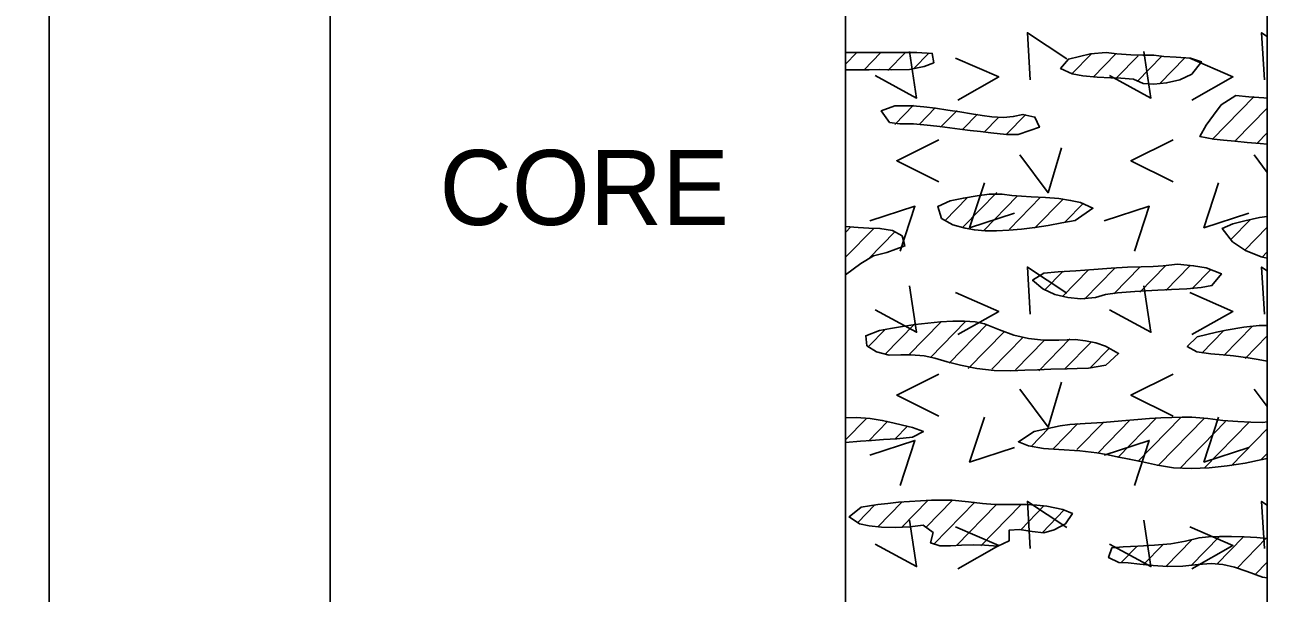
# Model space of a CAD drawing. Extents: x 0 to 0.833, y -0.32 to 0.608.
# Drawn here: x 0.7228 to 0.8333, y -0.1842 to -0.1337 of the extents above; entities that cross this region are included whole.
import ezdxf

# ---------------------------------------------------------------- set-up
doc = ezdxf.new("R2010")
doc.units = 0

msp = doc.modelspace()

# ---------------------------------------------------------------- linework, layer by layer
for points in [[(0, -0.32004), (0.83333, -0.32004), (0.83333, 0.60833), (0, 0.60833)], [(0.79583, -0.1377), (0.79676, -0.13771), (0.79792, -0.13769), (0.79882, -0.13766), (0.79992, -0.1377), (0.80151, -0.13766), (0.80282, -0.1374), (0.80367, -0.13708), (0.80354, -0.13624), (0.80216, -0.13616), (0.79583, -0.13616)], [(0.81822, -0.13835), (0.81944, -0.13841), (0.82033, -0.13845), (0.82145, -0.13852), (0.82229, -0.13893), (0.82324, -0.13897), (0.82438, -0.13887), (0.82555, -0.13858), (0.82662, -0.13808), (0.82749, -0.13698), (0.82651, -0.13668), (0.82524, -0.13658), (0.82413, -0.13651), (0.82324, -0.13641), (0.82226, -0.13639), (0.82121, -0.13636), (0.81995, -0.13627), (0.81902, -0.13616), (0.81761, -0.13629), (0.81566, -0.13674), (0.81496, -0.13758), (0.81598, -0.13807), (0.81695, -0.13824)], [(0.83305, -0.1402), (0.83171, -0.14009), (0.83054, -0.13999), (0.82925, -0.14081), (0.82857, -0.14172), (0.82792, -0.14261), (0.82735, -0.14364), (0.82858, -0.14386), (0.82945, -0.14396), (0.83045, -0.14406), (0.83155, -0.14416), (0.83272, -0.14425), (0.83333, -0.1443), (0.83333, -0.14021)], [(0.80066, -0.14251), (0.80188, -0.14251), (0.80339, -0.14264), (0.80423, -0.14274), (0.8051, -0.14285), (0.806, -0.14297), (0.80692, -0.14309), (0.80784, -0.1432), (0.80875, -0.14331), (0.81014, -0.14346), (0.81119, -0.14344), (0.81222, -0.1431), (0.81308, -0.14281), (0.81267, -0.14191), (0.8116, -0.14166), (0.81075, -0.14186), (0.80989, -0.14195), (0.80885, -0.14187), (0.80799, -0.14175), (0.80703, -0.14161), (0.806, -0.14145), (0.80492, -0.14128), (0.80384, -0.14112), (0.8028, -0.14099), (0.80182, -0.1409), (0.8002, -0.14089), (0.79901, -0.14136), (0.79974, -0.1424)], [(0.81233, -0.14901), (0.81063, -0.14889), (0.80977, -0.14876), (0.8086, -0.14875), (0.80755, -0.1489), (0.80632, -0.1491), (0.80513, -0.14934), (0.80403, -0.14986), (0.80436, -0.15092), (0.80536, -0.15149), (0.80647, -0.15179), (0.8073, -0.15194), (0.80824, -0.15201), (0.80926, -0.15202), (0.81035, -0.15197), (0.81149, -0.15187), (0.81267, -0.15172), (0.81386, -0.15154), (0.81506, -0.15132), (0.81625, -0.15109), (0.81783, -0.15001), (0.81673, -0.14951), (0.81585, -0.14931), (0.8148, -0.14915), (0.81361, -0.14905)], [(0.83265, -0.15082), (0.83136, -0.15113), (0.83028, -0.15141), (0.82934, -0.1518), (0.83026, -0.153), (0.83142, -0.15376), (0.83279, -0.15434), (0.83333, -0.15444), (0.83333, -0.15073)], [(0.79583, -0.15592), (0.79719, -0.15493), (0.79831, -0.15423), (0.79951, -0.15396), (0.80111, -0.15336), (0.80086, -0.15247), (0.80002, -0.152), (0.79889, -0.1518), (0.79791, -0.15177), (0.79694, -0.15171), (0.79583, -0.15163)], [(0.82537, -0.15498), (0.82408, -0.15513), (0.82319, -0.15518), (0.82214, -0.15521), (0.82091, -0.15525), (0.81947, -0.15534), (0.81792, -0.15546), (0.81632, -0.15558), (0.81475, -0.15567), (0.81348, -0.15577), (0.81247, -0.15641), (0.81337, -0.15717), (0.81444, -0.15768), (0.81561, -0.15796), (0.81675, -0.15807), (0.81807, -0.15796), (0.81896, -0.15768), (0.82003, -0.15754), (0.82157, -0.15742), (0.82253, -0.15736), (0.82362, -0.1573), (0.82483, -0.15724), (0.82618, -0.15717), (0.82745, -0.15706), (0.82842, -0.15689), (0.82927, -0.15583), (0.82791, -0.15532), (0.82679, -0.15512)], [(0.79885, -0.16089), (0.79763, -0.16135), (0.79773, -0.16224), (0.79859, -0.16277), (0.7997, -0.16306), (0.80074, -0.16305), (0.80165, -0.16304), (0.80281, -0.16312), (0.80377, -0.16333), (0.80486, -0.16368), (0.80606, -0.16397), (0.80751, -0.16425), (0.80905, -0.16443), (0.81052, -0.16447), (0.81177, -0.16441), (0.81289, -0.16437), (0.81408, -0.16433), (0.81553, -0.16429), (0.81642, -0.16427), (0.81745, -0.16423), (0.81897, -0.16396), (0.82011, -0.16292), (0.81896, -0.16226), (0.8181, -0.16199), (0.81717, -0.16179), (0.81626, -0.16169), (0.81479, -0.16175), (0.81343, -0.16174), (0.8121, -0.16159), (0.8108, -0.16129), (0.80953, -0.16083), (0.8082, -0.16028), (0.80736, -0.16012), (0.8064, -0.16005), (0.80536, -0.16005), (0.80427, -0.16011), (0.80314, -0.16022), (0.80201, -0.16036), (0.8009, -0.16053), (0.79984, -0.16071)], [(0.83263, -0.16044), (0.83126, -0.16058), (0.82969, -0.16084), (0.82883, -0.16102), (0.82712, -0.16143), (0.82623, -0.1623), (0.82708, -0.16279), (0.82831, -0.16297), (0.82941, -0.16304), (0.83033, -0.16313), (0.83165, -0.16331), (0.83253, -0.16345), (0.83333, -0.1636), (0.83333, -0.16045)], [(0.79583, -0.17084), (0.79715, -0.17073), (0.79814, -0.17066), (0.79922, -0.17058), (0.80039, -0.1705), (0.80179, -0.17037), (0.80275, -0.16986), (0.80179, -0.16952), (0.80091, -0.1693), (0.80003, -0.16908), (0.79909, -0.16888), (0.79803, -0.16871), (0.79677, -0.16862), (0.79583, -0.16864)], [(0.82816, -0.17309), (0.82978, -0.17292), (0.83137, -0.17267), (0.8329, -0.17236), (0.83333, -0.17225), (0.83333, -0.16901), (0.83295, -0.16905), (0.83188, -0.16902), (0.83071, -0.16897), (0.82938, -0.16887), (0.82807, -0.1687), (0.82662, -0.16858), (0.82576, -0.16858), (0.82484, -0.16861), (0.82387, -0.16866), (0.82286, -0.16872), (0.82182, -0.1688), (0.82077, -0.16889), (0.81973, -0.16897), (0.81872, -0.16905), (0.81715, -0.16914), (0.81579, -0.16923), (0.81491, -0.16937), (0.81357, -0.16964), (0.8126, -0.16985), (0.81121, -0.17077), (0.8121, -0.17113), (0.81345, -0.17138), (0.81479, -0.17147), (0.81668, -0.17157), (0.81818, -0.17177), (0.81905, -0.17192), (0.82, -0.1721), (0.82107, -0.17231), (0.82225, -0.17257), (0.82357, -0.17286), (0.82501, -0.17308), (0.82656, -0.17315)], [(0.79708, -0.17807), (0.79794, -0.17825), (0.79904, -0.17836), (0.80028, -0.1784), (0.80156, -0.17834), (0.80274, -0.17819), (0.80361, -0.17885), (0.80338, -0.17975), (0.80422, -0.18002), (0.80517, -0.18003), (0.80613, -0.17998), (0.8072, -0.17995), (0.80818, -0.17998), (0.80939, -0.18005), (0.81037, -0.17959), (0.81038, -0.17864), (0.8113, -0.17858), (0.81244, -0.17876), (0.81346, -0.17887), (0.81438, -0.17862), (0.81539, -0.17807), (0.81601, -0.17716), (0.81517, -0.17679), (0.81374, -0.17651), (0.81285, -0.17642), (0.81187, -0.17636), (0.81, -0.17636), (0.8091, -0.17634), (0.808, -0.17627), (0.80678, -0.17611), (0.8053, -0.17598), (0.80443, -0.17597), (0.80349, -0.17598), (0.80251, -0.17602), (0.80152, -0.17608), (0.80054, -0.17616), (0.79959, -0.17625), (0.7987, -0.17635), (0.79722, -0.17658), (0.79614, -0.17745)], [(0.83241, -0.17929), (0.83129, -0.17923), (0.83017, -0.17919), (0.8291, -0.17919), (0.82811, -0.17923), (0.82728, -0.17931), (0.82608, -0.17961), (0.82476, -0.17984), (0.8233, -0.17998), (0.82183, -0.18006), (0.82051, -0.18012), (0.81951, -0.18022), (0.81922, -0.18108), (0.82013, -0.1815), (0.82097, -0.18155), (0.822, -0.18165), (0.82318, -0.18178), (0.82448, -0.18187), (0.82584, -0.18184), (0.82719, -0.18168), (0.82836, -0.18161), (0.8294, -0.18169), (0.83043, -0.18193), (0.83156, -0.18232), (0.83291, -0.18281), (0.83333, -0.18288), (0.83333, -0.17937)]]:
    msp.add_lwpolyline(points, close=True)
for points in [[(0.725, 0.55417), (0.725, -0.27517)], [(0.75, 0.55417), (0.75, -0.27517)], [(0.75, 0.55417), (0.75, -0.27517)], [(0.79583, 0.55417), (0.79583, -0.27517)], [(0.725, 0.54167), (0.725, -0.27517)], [(0.83333, -0.27517), (0.83333, 0.50377)], [(0.81551, -0.13672), (0.81201, -0.13441), (0.81226, -0.1386)], [(0.83333, -0.13473), (0.83284, -0.13441), (0.83309, -0.1386)], [(0.79583, -0.13719), (0.79681, -0.13618)], [(0.79898, -0.13617), (0.79747, -0.13772)], [(0.79847, -0.13821), (0.80215, -0.14021), (0.80153, -0.13608)], [(0.80116, -0.13615), (0.79959, -0.13776)], [(0.80328, -0.13619), (0.80188, -0.13762)], [(0.80562, -0.13666), (0.80946, -0.13834), (0.80581, -0.14041)], [(0.8177, -0.13629), (0.81596, -0.13807)], [(0.81988, -0.13627), (0.81785, -0.13835)], [(0.8193, -0.13821), (0.82299, -0.14021), (0.82236, -0.13608)], [(0.82185, -0.13646), (0.81997, -0.13839)], [(0.824, -0.13647), (0.82178, -0.13875)], [(0.82601, -0.13663), (0.82378, -0.13891)], [(0.82645, -0.13666), (0.83029, -0.13834), (0.82664, -0.14041)], [(0.83217, -0.14008), (0.82844, -0.14389)], [(0.80188, -0.14085), (0.8002, -0.14257)], [(0.8038, -0.14109), (0.80237, -0.14256)], [(0.80575, -0.14131), (0.80429, -0.1428)], [(0.83333, -0.1411), (0.83052, -0.14398)], [(0.80758, -0.14165), (0.80627, -0.14299)], [(0.80941, -0.14198), (0.80816, -0.14326)], [(0.81188, -0.14167), (0.81016, -0.14342)], [(0.83333, -0.14331), (0.83245, -0.14421)], [(0.80412, -0.14392), (0.80038, -0.14579), (0.80412, -0.14767)], [(0.81134, -0.14526), (0.81384, -0.14863), (0.81503, -0.14463)], [(0.82496, -0.14392), (0.82121, -0.14579), (0.82496, -0.14767)], [(0.83217, -0.14526), (0.83333, -0.14682)], [(0.80818, -0.14775), (0.80687, -0.15175), (0.81087, -0.15044)], [(0.82901, -0.14775), (0.8277, -0.15175), (0.8317, -0.15044)], [(0.80465, -0.15113), (0.80667, -0.14905)], [(0.80626, -0.15169), (0.80928, -0.1486)], [(0.80809, -0.15203), (0.81111, -0.14893)], [(0.81041, -0.15186), (0.81318, -0.14903)], [(0.80069, -0.15383), (0.802, -0.14983), (0.798, -0.15114)], [(0.81264, -0.15179), (0.81518, -0.14919)], [(0.81536, -0.15122), (0.81699, -0.14955)], [(0.82152, -0.15383), (0.82284, -0.14983), (0.81884, -0.15114)], [(0.8301, -0.15279), (0.83184, -0.15101)], [(0.7963, -0.15167), (0.79583, -0.15216)], [(0.79834, -0.1518), (0.79583, -0.15437)], [(0.79786, -0.1545), (0.80023, -0.15208)], [(0.83131, -0.15376), (0.83333, -0.15169)], [(0.83285, -0.15439), (0.83333, -0.1539)], [(0.81551, -0.15756), (0.81201, -0.15524), (0.81226, -0.15943)], [(0.81519, -0.15561), (0.81354, -0.1573)], [(0.81514, -0.15787), (0.81748, -0.15547)], [(0.81709, -0.15809), (0.81974, -0.15537)], [(0.8197, -0.15763), (0.82203, -0.15523)], [(0.82202, -0.15747), (0.8243, -0.15513)], [(0.82431, -0.15733), (0.82644, -0.15514)], [(0.82663, -0.15717), (0.82834, -0.15542)], [(0.83333, -0.15557), (0.83284, -0.15524), (0.83309, -0.15943)], [(0.79847, -0.15904), (0.80215, -0.16104), (0.80153, -0.15691)], [(0.80562, -0.15749), (0.80946, -0.15918), (0.80581, -0.16124)], [(0.8193, -0.15904), (0.82299, -0.16104), (0.82236, -0.15691)], [(0.82645, -0.15749), (0.83029, -0.15918), (0.82664, -0.16124)], [(0.80142, -0.16308), (0.8043, -0.16013)], [(0.80653, -0.16005), (0.8034, -0.16327)], [(0.79938, -0.16075), (0.79786, -0.1623)], [(0.79933, -0.16301), (0.80195, -0.16032)], [(0.80506, -0.16378), (0.8084, -0.16036)], [(0.80997, -0.16096), (0.80675, -0.16426)], [(0.82751, -0.1629), (0.82945, -0.16092)], [(0.83203, -0.16049), (0.82949, -0.16309)], [(0.81164, -0.16146), (0.80884, -0.16433)], [(0.81353, -0.16174), (0.81094, -0.16439)], [(0.81303, -0.16446), (0.81579, -0.16163)], [(0.81534, -0.1643), (0.81768, -0.16191)], [(0.8176, -0.1642), (0.81934, -0.16242)], [(0.83138, -0.16337), (0.83333, -0.16136)], [(0.83333, -0.16358), (0.83333, -0.16358)], [(0.80412, -0.16475), (0.80038, -0.16663), (0.80412, -0.1685)], [(0.81134, -0.16609), (0.81384, -0.16947), (0.81503, -0.16547)], [(0.82496, -0.16475), (0.82121, -0.16663), (0.82496, -0.1685)], [(0.83217, -0.16609), (0.83333, -0.16765)], [(0.79765, -0.16873), (0.79583, -0.1706)], [(0.7996, -0.16895), (0.79786, -0.17073)], [(0.80818, -0.16858), (0.80687, -0.17258), (0.81087, -0.17127)], [(0.8164, -0.17147), (0.81879, -0.16902)], [(0.81829, -0.17175), (0.82114, -0.16883)], [(0.82004, -0.17217), (0.82346, -0.16867)], [(0.82569, -0.16859), (0.82184, -0.17253)], [(0.82775, -0.16869), (0.8237, -0.17284)], [(0.82964, -0.16896), (0.82557, -0.17314)], [(0.82901, -0.16858), (0.8277, -0.17258), (0.8317, -0.17127)], [(0.83173, -0.16903), (0.82774, -0.17312)], [(0.8013, -0.16942), (0.80027, -0.17048)], [(0.81392, -0.16958), (0.81235, -0.17119)], [(0.8143, -0.17141), (0.8165, -0.16916)], [(0.83333, -0.16961), (0.83012, -0.1729)], [(0.80069, -0.17466), (0.802, -0.17066), (0.798, -0.17198)], [(0.82152, -0.17466), (0.82284, -0.17066), (0.81884, -0.17198)], [(0.83281, -0.17236), (0.83333, -0.17182)], [(0.79844, -0.17639), (0.79691, -0.17796)], [(0.79871, -0.17833), (0.80085, -0.17614)], [(0.80083, -0.17837), (0.80311, -0.17603)], [(0.80534, -0.17596), (0.80299, -0.17837)], [(0.80367, -0.17988), (0.80732, -0.17614)], [(0.80571, -0.18), (0.80924, -0.17639)], [(0.81142, -0.17637), (0.80785, -0.18002)], [(0.81141, -0.1786), (0.81348, -0.17647)], [(0.81551, -0.17839), (0.81201, -0.17608), (0.81226, -0.18026)], [(0.83333, -0.1764), (0.83284, -0.17608), (0.83309, -0.18026)], [(0.79847, -0.17987), (0.80215, -0.18187), (0.80153, -0.17775)], [(0.81528, -0.17684), (0.81331, -0.17886)], [(0.8193, -0.17987), (0.82299, -0.18187), (0.82236, -0.17775)], [(0.80562, -0.17833), (0.80946, -0.18001), (0.80581, -0.18207)], [(0.82645, -0.17833), (0.83029, -0.18001), (0.82664, -0.18207)], [(0.82035, -0.18151), (0.82176, -0.18006)], [(0.82233, -0.18169), (0.82408, -0.1799)], [(0.82433, -0.18186), (0.82666, -0.17947)], [(0.82909, -0.17919), (0.82656, -0.18178)], [(0.82885, -0.18165), (0.83122, -0.17922)], [(0.83325, -0.17936), (0.83065, -0.18202)], [(0.83333, -0.18148), (0.83227, -0.18258)]]:
    msp.add_lwpolyline(points)

# ---------------------------------------------------------------- texts
msp.add_text('CORE', height=0.006667).set_placement((0.75971, -0.1515))

doc.saveas('drawing.dxf')
